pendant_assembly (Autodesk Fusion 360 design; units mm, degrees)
part number: 2026-10-16-18-08-27-182
part number: 2026-10-16-18-08-27-372
part number: 2026-10-16-18-08-27-570
part number: 2026-10-16-18-08-27-606
part number: 2026-10-16-18-08-27-752
part number: 2026-10-16-18-08-27-795
part number: 2026-10-16-18-08-29-178
parameter "p_L" = 83 comment "job c8821a4f"
parameter "p_Dtop" = 12.5 comment "job c8821a4f"
parameter "p_Dtip" = 7 comment "job c8821a4f"
parameter "p_cone" = 18 comment "job c8821a4f"
parameter "p_bore" = 8 comment "job c8821a4f"
parameter "p_boreDepth" = 65 comment "job c8821a4f"
parameter "p_chan" = 2 comment "job c8821a4f"
parameter "p_chanEnd" = 3 comment "job c8821a4f"
parameter "p_neckD" = 11 comment "job c8821a4f"
parameter "p_neckH" = 3 comment "job c8821a4f"
parameter "p_flangeD" = 12.5 comment "job c8821a4f"
parameter "p_flangeH" = 1.5 comment "job c8821a4f"
parameter "p_stubD" = 10 comment "job c8821a4f"
parameter "p_flat" = 0.6 comment "job c8821a4f"
parameter "p_sliderD" = 7.9 comment "job c8821a4f"
parameter "p_sliderL" = 55 comment "job c8821a4f"
parameter "p_protrude" = 6.5 comment "job c8821a4f"
parameter "p_stroke" = 6 comment "job c8821a4f"
parameter "p_lockLen" = 3.5 comment "job c8821a4f"
parameter "p_hook" = 0.5 comment "job c8821a4f"
parameter "p_grooveW" = 1.6 comment "job c8821a4f"
parameter "p_grooveD" = 1 comment "job c8821a4f"
parameter "p_pinD" = 1.5 comment "job c8821a4f"
parameter "p_pinL" = 3.2 comment "job c8821a4f"
parameter "p_pinZ" = 75 comment "job c8821a4f"
parameter "p_springOD" = 7.5 comment "job c8821a4f"
parameter "p_springWire" = 0.6 comment "job c8821a4f"
parameter "p_springFree" = 18 comment "job c8821a4f"
parameter "p_springTurns" = 10 comment "job c8821a4f"
parameter "p_holeD" = 1.2 comment "job c8821a4f"
parameter "p_holeZ" = 5 comment "job c8821a4f"
parameter "p_ringT" = 2.5 comment "job c8821a4f"
parameter "p_ringOD" = 15 comment "job c8821a4f"
parameter "p_eyeD" = 3 comment "job c8821a4f"
sketch "ShellProfile" plane through (0, 0, 0) normal (0, 1, 0) x axis (1, 0, 0)
  line L1 (3.5, 0) -> (0, 0)
  line L2 (6.25, -18) -> (3.5, 0)
  line L3 (6.25, -78.5) -> (6.25, -18)
  line L4 (5.5, -78.5) -> (6.25, -78.5)
  line L5 (5.5, -81.5) -> (5.5, -78.5)
  line L6 (5, -81.5) -> (5.5, -81.5)
  line L7 (5, -83) -> (5, -81.5)
  line L8 (0, -83) -> (5, -83)
  line L9 (0, 0) -> (0, -83)
revolve "Revolve1" sketch "ShellProfile" AlongAngle 360 bodies "Shell"
sketch "Bore" plane through (0, 0, 0) normal (0, 1, 0) x axis (1, 0, 0)
  line L1 (4, -18) -> (0, -15.5966)
  line L2 (4, -84) -> (4, -18)
  line L3 (0, -84) -> (4, -84)
  line L4 (0, -15.5966) -> (0, -84)
revolve "Revolve2" sketch "Bore" + "PinHole" AlongAngle 360
sketch "Channel" plane through (0, 0, 0) normal (0, 1, 0) x axis (1, 0, 0)
  line L1 (1, -3) -> (0, -3)
  line L2 (1, -18) -> (1, -3)
  line L3 (0, -18) -> (1, -18)
  line L4 (0, -3) -> (0, -18)
revolve "Revolve3" sketch "Channel" + "PinHole" AlongAngle 360
sketch "VentHole" plane through (0, 0, 0) normal (0, 1, 0) x axis (1, 0, 0)
  circle C1 centre (0, -5) radius 0.6
extrude "Extrude1" cut sketch "VentHole" + "PinHole" profile of S1:C1 distance 6
circular_pattern "C-Pattern1" TotalAngle 360
work_plane "WorkPlane1" AlongDistance 0 ExtraOffset 0
sketch "FlatBody" plane through (0, 0, 0) normal (0, 0, 1) x axis (1, 0, 0)
  line L1 (7.25, -7.25) -> (5.65, -7.25)
  line L2 (7.25, 7.25) -> (7.25, -7.25)
  line L3 (5.65, 7.25) -> (7.25, 7.25)
  line L4 (5.65, -7.25) -> (5.65, 7.25)
extrude "Extrude2" cut sketch "FlatBody" + "PinHole" profile of S1:L1 S1:L2 S1:L3 S1:L4 blind 78.5
work_plane "WorkPlane2" AlongDistance 78.5 ExtraOffset 0
sketch "FlatNeck" plane through (0, 0, 78.5) normal (0, 0, 1) x axis (1, 0, 0)
  line L1 (7.25, -7.25) -> (4.9, -7.25)
  line L2 (7.25, 7.25) -> (7.25, -7.25)
  line L3 (4.9, 7.25) -> (7.25, 7.25)
  line L4 (4.9, -7.25) -> (4.9, 7.25)
extrude "Extrude3" cut sketch "FlatNeck" + "PinHole" profile of S1:L1 S1:L2 S1:L3 S1:L4 blind 3
work_plane "WorkPlane3" AlongDistance -4.75 ExtraOffset 0
sketch "PinHole" plane through (-4.75, 0, 0) normal (1, 0, 0) x axis (0, 0, -1)
  circle C1 centre (-75, 0) radius 0.75
extrude "Extrude4" cut sketch "PinHole" distance 1.75
place_component sketch "FlangeProfile"
sketch "FlangeProfile" plane through (0, 0, 0) normal (0, 1, 0) x axis (1, 0, 0)
  line L1 (6.25, -81.5) -> (5, -81.5)
  line L2 (6.25, -83) -> (6.25, -81.5)
  line L3 (5, -83) -> (6.25, -83)
  line L4 (5, -81.5) -> (5, -83)
revolve "Revolve1" sketch "FlangeProfile" AlongAngle 360 bodies "Flange"
sketch "SliderProfile" plane through (0, 0, 0) normal (0, 1, 0) x axis (1, 0, 0)
  line L1 (3.95, -34.5) -> (0, -34.5)
  line L2 (3.95, -89) -> (3.95, -34.5)
  line L3 (3.45, -89.5) -> (3.95, -89)
  line L4 (0, -89.5) -> (3.45, -89.5)
  line L5 (0, -34.5) -> (0, -89.5)
revolve "Revolve1" sketch "SliderProfile" AlongAngle 360 bodies "Slider"
work_plane "WorkPlane1" AlongDistance 74.2 ExtraOffset 0
sketch "GrooveVertical" plane through (0, 0, 74.2) normal (0, 0, 1) x axis (1, 0, 0)
  line L1 (-2.95, -0.8) -> (-6.25, -0.8)
  line L2 (-2.95, 0.8) -> (-2.95, -0.8)
  line L3 (-6.25, 0.8) -> (-2.95, 0.8)
  line L4 (-6.25, -0.8) -> (-6.25, 0.8)
extrude "Extrude1" cut sketch "GrooveVertical" + "PinHole" profile of S1:L1 S1:L2 S1:L3 S1:L4 blind 7.6
work_plane "WorkPlane2" AlongDistance 80.2 ExtraOffset 0
sketch "GrooveLock" plane through (0, 0, 80.2) normal (0, 0, 1) x axis (1, 0, 0)
  line L1 (-6.0216, 1.6742) -> (-2.8422, 0.7902)
  line L2 (-2.5115, -5.7232) -> (-1.1855, -2.7013)
  arc A1 centre (0, 0) radius 2.95 clockwise from (-1.1855, -2.7013) to (-2.8422, 0.7902)
  arc A2 centre (0, 0) radius 6.25 clockwise from (-2.5115, -5.7232) to (-6.0216, 1.6742)
extrude "Extrude2" cut sketch "GrooveLock" + "PinHole" profile of S1:A1 S1:A2 S1:L1 S1:L2 blind 1.6
work_plane "WorkPlane3" AlongDistance 79.7 ExtraOffset 0
sketch "GrooveHook" plane through (0, 0, 79.7) normal (0, 0, 1) x axis (1, 0, 0)
  line L1 (-5.1052, -3.6054) -> (-2.4097, -1.7018)
  line L2 (-2.5115, -5.7232) -> (-1.1855, -2.7013)
  arc A1 centre (0, 0) radius 2.95 clockwise from (-1.1855, -2.7013) to (-2.4097, -1.7018)
  arc A2 centre (0, 0) radius 6.25 clockwise from (-2.5115, -5.7232) to (-5.1052, -3.6054)
extrude "Extrude3" cut sketch "GrooveHook" + "PinHole" profile of S1:A1 S1:A2 S1:L1 S1:L2 blind 2.1
work_plane "WorkPlane1" AlongDistance -4.65 ExtraOffset 0
sketch "Pin" plane through (-4.65, 0, 0) normal (1, 0, 0) x axis (0, 0, -1)
  circle C1 centre (-75, 0) radius 0.75
extrude "Extrude1" new body sketch "Pin" distance 1.6 bodies "GuidePin"
sketch "Helix" plane through (0, 0, 0) normal (0, 0, 1) x axis (1, 0, 0)
  curve K1 (3.45, 0) -> (3.45, 0)
work_plane "WorkPlane1" ExtraOffset 0
sketch "Sketch2" plane through (3.45, 0, 18.3) normal (-0.0011, 0.9974, 0.0723) x axis (0.0001, -0.0723, 0.9974)
  circle C1 centre (0, 0) radius 0.3
sweep "Sweep1" sketch "Sketch2" TwistAngle 0 TaperAngle 0 bodies "Spring"
work_plane "WorkPlane1" AlongDistance 78.75 ExtraOffset 0
sketch "Sketch1" plane through (0, 0, 78.75) normal (0, 0, 1) x axis (1, 0, 0)
  circle C1 centre (0, 0) radius 7.5
extrude "Extrude1" new body sketch "Sketch1" along normal blind 2.5 bodies "BailRing"
sketch "Sketch2" plane through (0, 0, 78.75) normal (0, 0, 1) x axis (1, 0, 0)
  circle C1 centre (0, 0) radius 5.6
extrude "Extrude2" cut sketch "Sketch2" + "PinHole" profile of S1:C1 blind 2.5
sketch "RingFlat" plane through (0, 0, 78.75) normal (0, 0, 1) x axis (1, 0, 0)
  line L1 (5.7, -3) -> (5, -3)
  line L2 (5.7, 3) -> (5.7, -3)
  line L3 (5, 3) -> (5.7, 3)
  line L4 (5, -3) -> (5, 3)
extrude "Extrude3" add sketch "RingFlat" + "PinHole" profile of S1:L1 S1:L2 S1:L3 S1:L4 blind 2.5
sketch "Lug" plane through (0, 0, 78.75) normal (0, 0, 1) x axis (1, 0, 0)
  line L1 (12.6, -1.25) -> (6.6, -1.25)
  line L2 (12.6, 1.25) -> (12.6, -1.25)
  line L3 (6.6, 1.25) -> (12.6, 1.25)
  line L4 (6.6, -1.25) -> (6.6, 1.25)
extrude "Extrude4" add sketch "Lug" + "PinHole" profile of S1:L1 S1:L2 S1:L3 S1:L4 blind 9.75
sketch "Eye" plane through (0, 0, 0) normal (0, 1, 0) x axis (1, 0, 0)
  circle C1 centre (9.6, -86) radius 1.5
extrude "Extrude5" cut sketch "Eye" + "PinHole" profile of S1:C1 distance 3
as_built_joint "As-built1"
as_built_joint "As-built2"
as_built_joint "As-built3"
as_built_joint "As-built4"
as_built_joint "As-built5" RotateMinimum -50.8 RotateMaximum 0 SlideMinimum -6 SlideMaximum 0
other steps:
create_component "CreateComponent1"
create_component "CreateComponent2" sketch "FlangeProfile"
create_component "CreateComponent3"
create_component "CreateComponent4"
create_component "CreateComponent5"
create_component "CreateComponent6"
named bodies: "Shell", "Flange", "Slider", "GuidePin", "Spring", "BailRing"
